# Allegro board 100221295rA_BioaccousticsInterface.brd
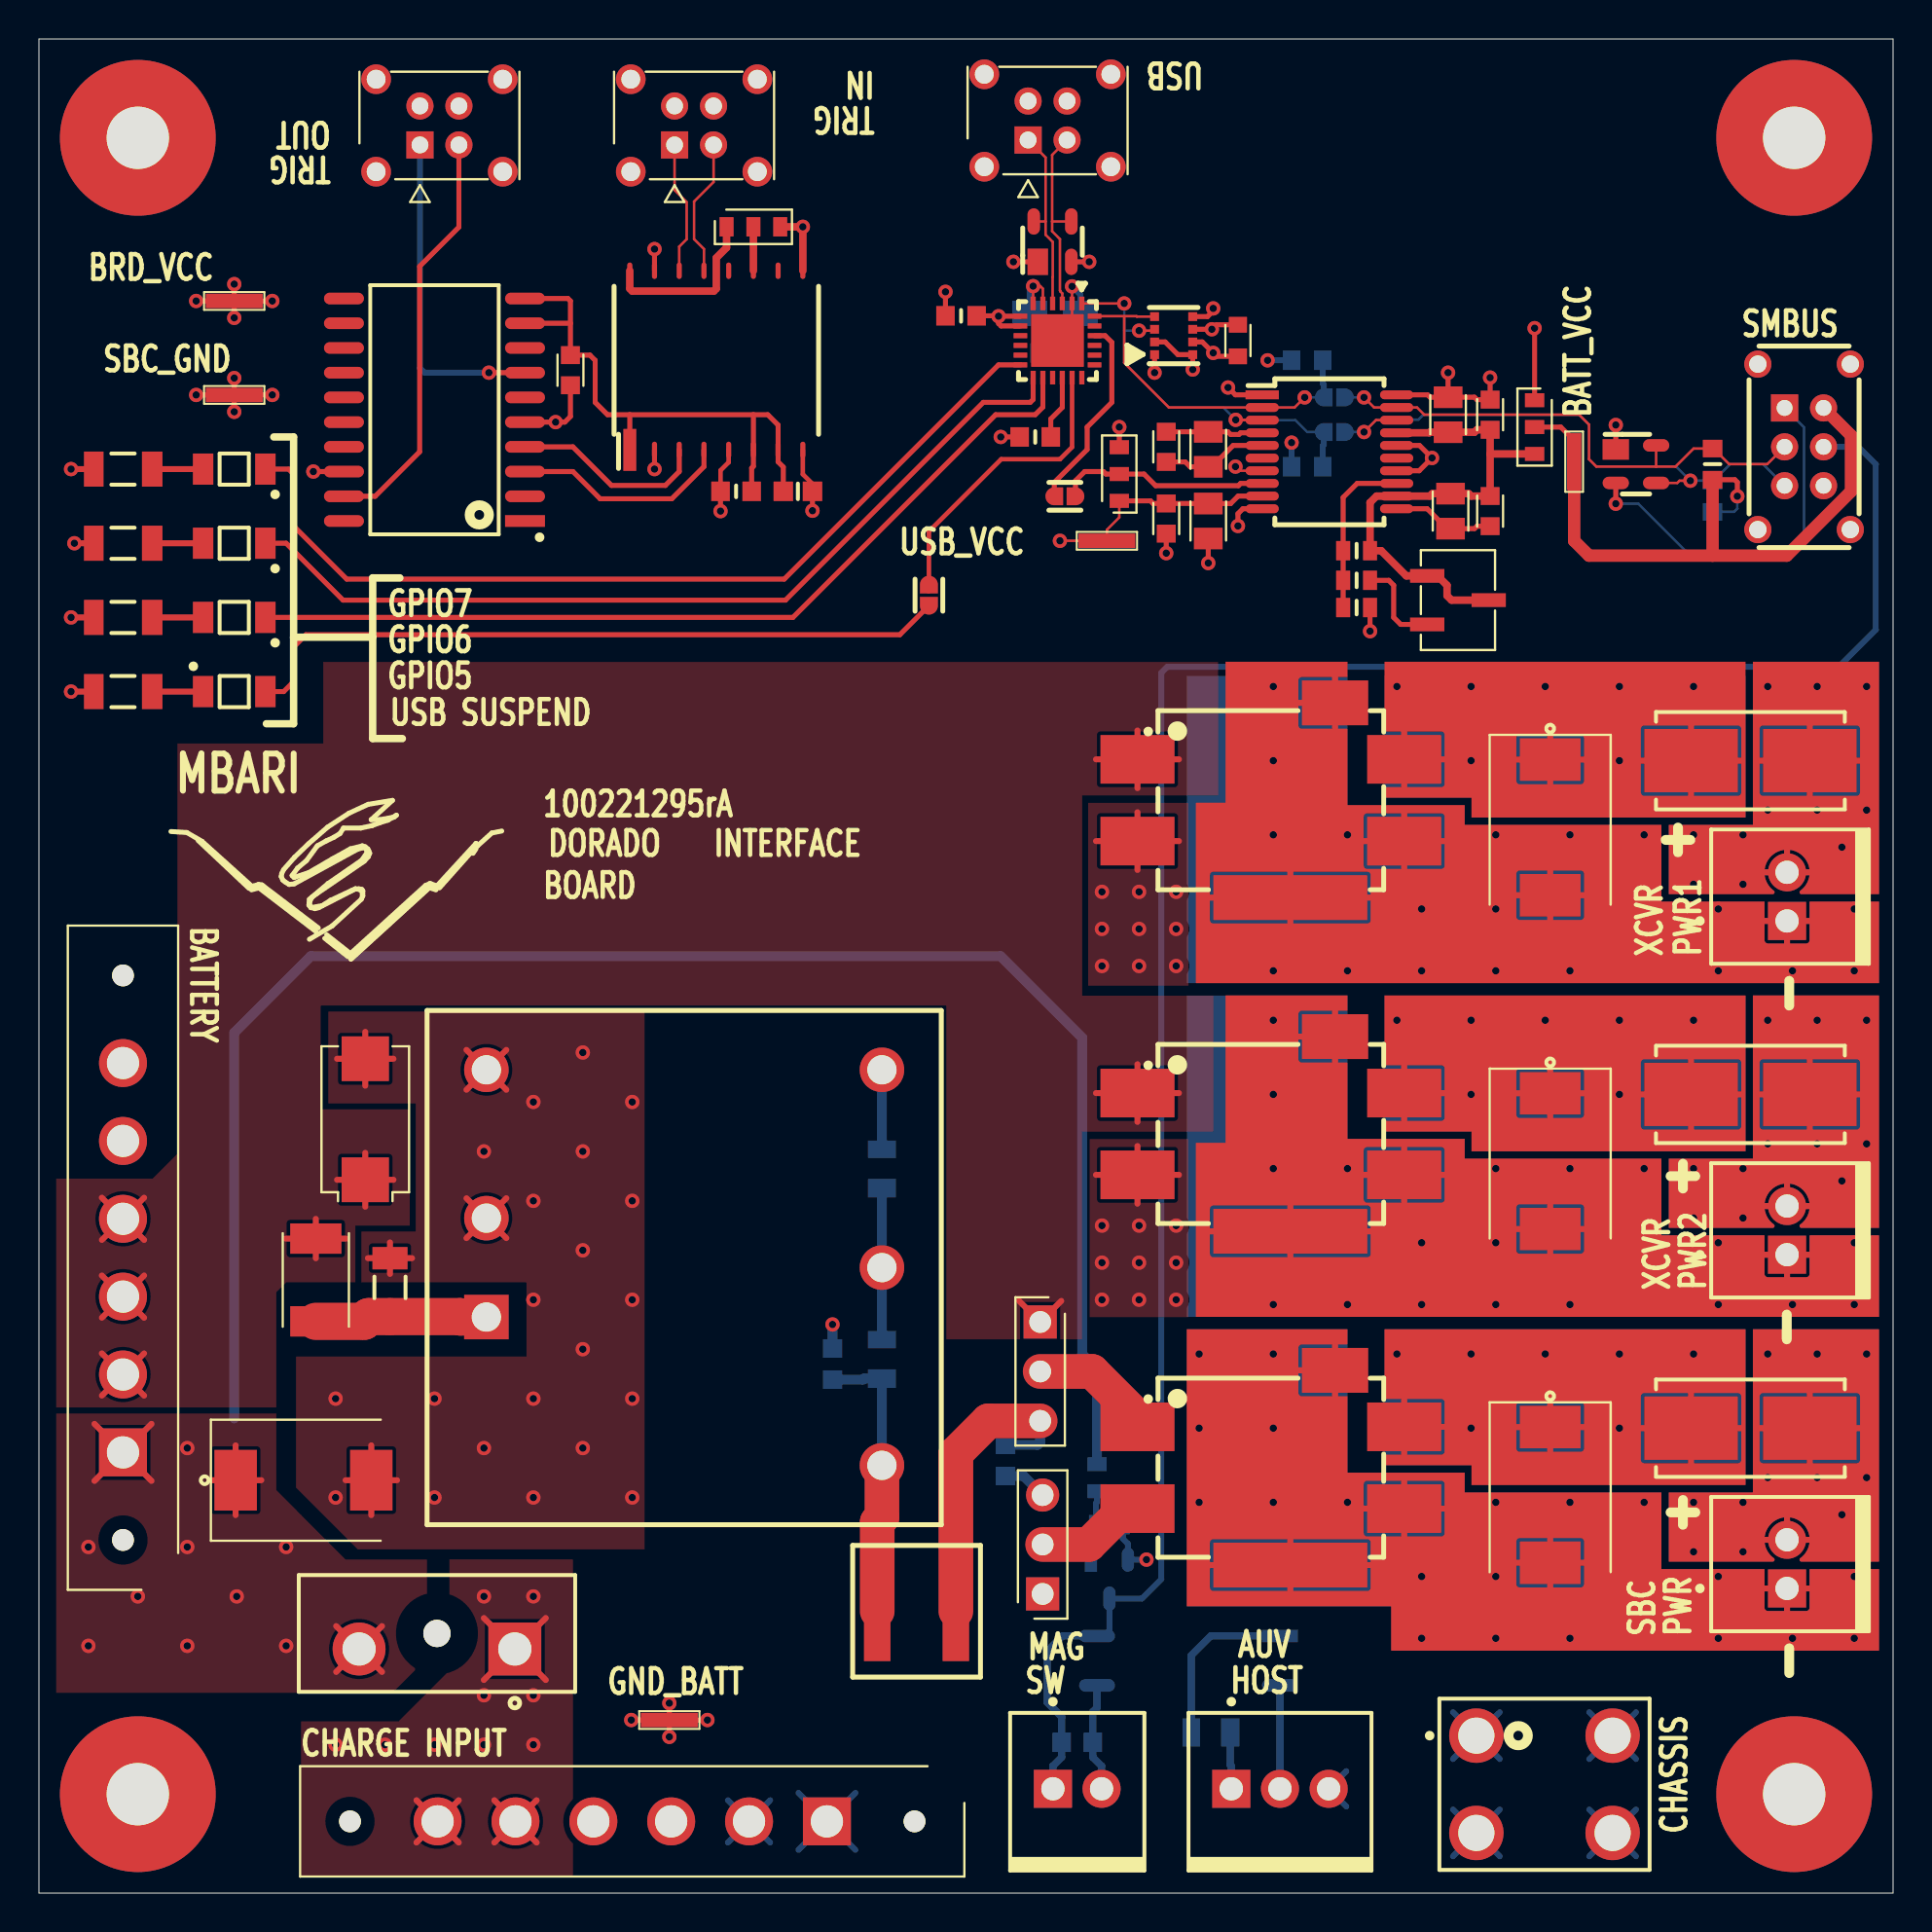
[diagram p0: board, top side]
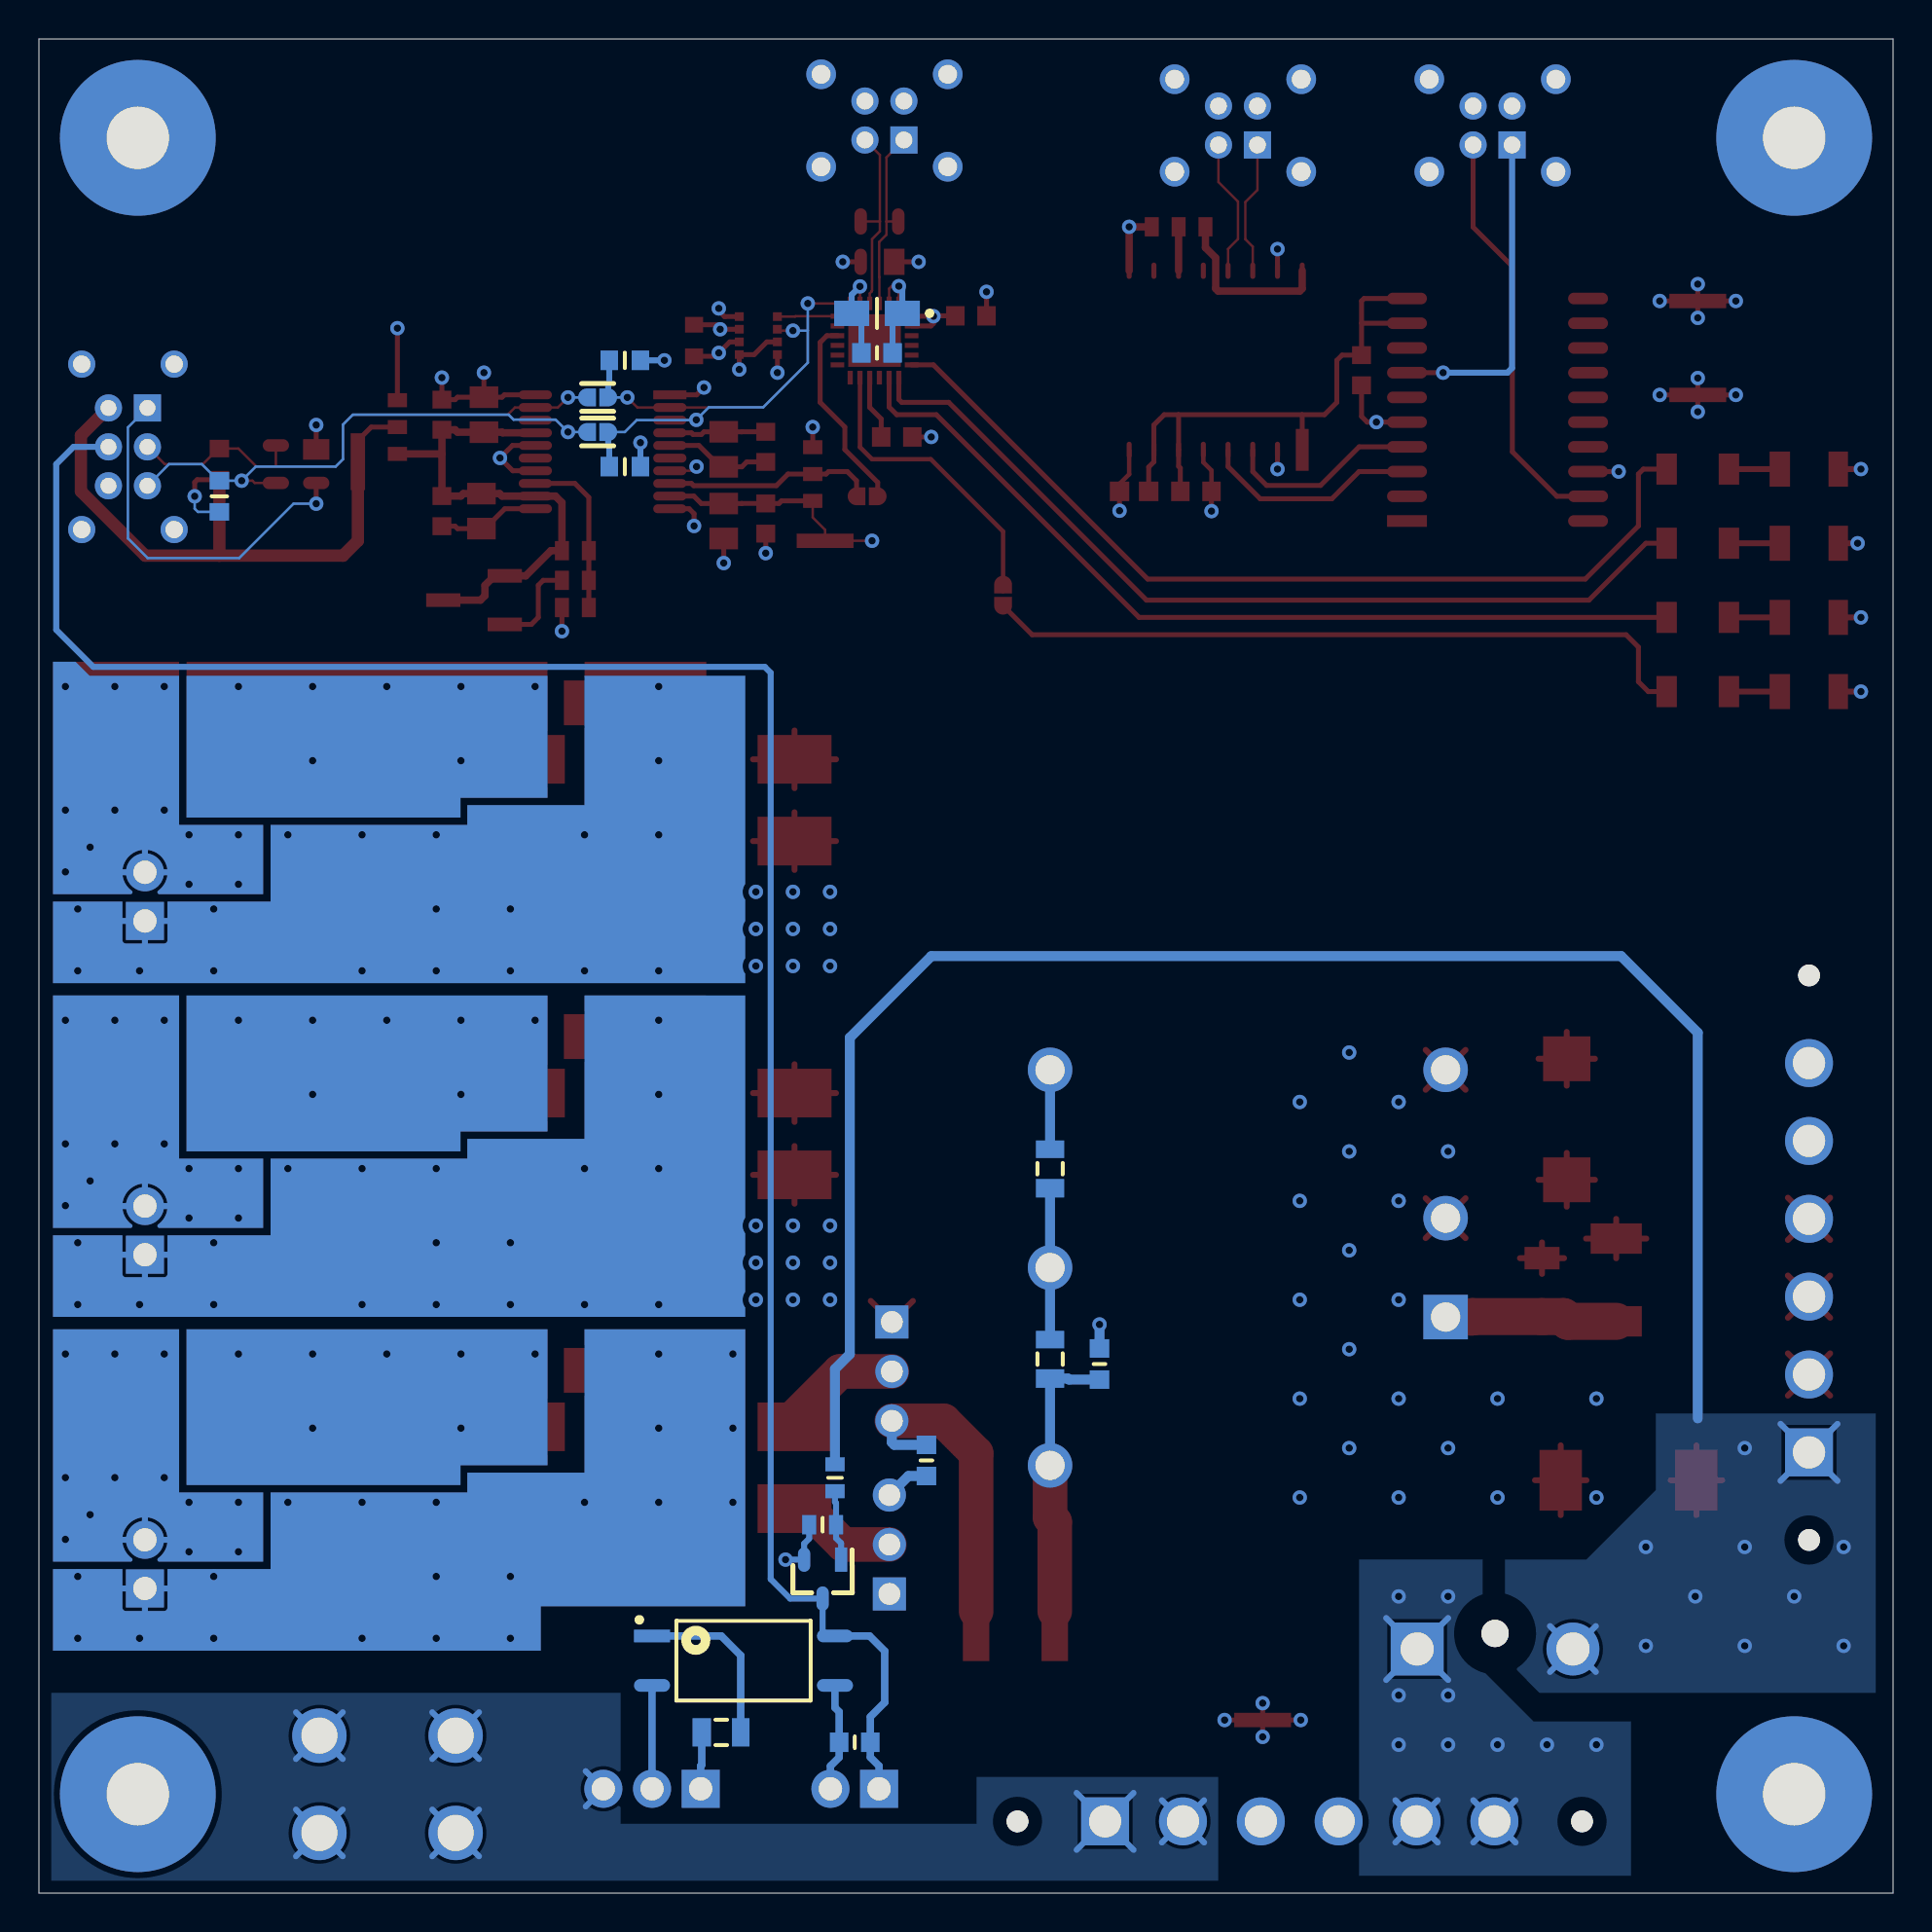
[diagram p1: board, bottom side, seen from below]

Outline 95.25 x 95.25 mm; copper layers: TOP, IN1, IN2, BOTTOM. Coordinates in mm from the lower left corner of the outline.
Outline path: 0,95.25 95.25,95.25 95.25,0 0,0 0,95.25

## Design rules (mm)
constraint set DEFAULT: min track width 0.127
net group AUV_BATT+: nets AUV_BATT+ N29578
net group BRD.SCL: nets BRD.SCL BRD.SDA
net group N26994: nets N26994 N26998
net group 3V3_ISO: nets 3V3_ISO N26987 N27684 N305001
net group BATT.SCL: nets BATT.SCL BATT.SDA BATT.VCC
net group BATT[0..4]: nets BATT.RESET
net group BATT_CHARGE: nets BATT_DISABLE N03532 N27268
net group BRD[0..4]: nets BRD.RESET
net group N02850: nets N02850 N03943 N21370
net group USB[0..3]: nets USB.D+ USB.D- USB.VCC

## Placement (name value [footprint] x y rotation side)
C1  1.0uF  [CAPC1608X90N]  53.34 7.75 0 bottom
C2  47uF  [CAPMP7343X430N]  16.76 39.75 90 top
C3  10uF  [CAPC3216X180N]  18.03 31.11 90 top
C4  1.0uF  [CAPC1608X90N]  40.77 27.18 90 bottom
C5  0.1uF  [CAPC1608X90N]  49.66 22.23 270 bottom
C6  4.7uF  [CAPMP3216X120N]  52.2 81.15 0 bottom
C7  0.1uF  [CAPC1608X90N]  52.2 79.12 0 bottom
C8  4.7uF  [CAPC1608X90N]  51.18 74.8 180 top
C9  0.1uF  [CAPC1608X90N]  47.37 81.03 180 top
C10  10uF  [CAPC2012X145L45N]  60.07 74.17 270 top
C11  0.10uF  [CAPC1608X87N]  57.91 74.3 270 top
C12  0.10uF  [CAPC1608X87N]  74.55 70.99 270 top
C13  10uF  [CAPC2012X145L45N]  72.52 70.99 270 top
C14  10uF  [CAPC2012X145L45N]  60.07 70.48 270 top
C15  0.10uF  [CAPC1608X87N]  57.91 70.61 270 top
C16  0.10uF  [CAPC1608X87N]  74.55 75.95 90 top
C17  10uF  [CAPC2012X145L45N]  72.39 75.95 90 top
C18  0.1uF  [CAPC1608X90N]  35.81 72.01 180 top
C19  10uF  [CAPC1608X100N]  38.99 72.01 0 top
C20  0.10uF  [CAPC1608X87N]  27.3 78.23 270 top
C21  0.1uF  [CAPC1608X80L30N]  61.59 79.76 270 top
D1  SMDJ22A  [DIOM7959X262N]  13.59 21.21 0 top
D2  SMDJ22A  [DIOM7959X262N]  77.64 54.74 270 top
D3  SMDJ22A  [DIOM7959X262N]  77.64 37.6 270 top
D4  SMDJ22A  [DIOM7959X262N]  77.64 20.45 270 top
D5  LTST-C150EKT  [LED_LTST-C150XXX]  10.03 65.53 180 top
D6  LTST-C150AKT  [LED_LTST-C150XXX]  10.03 69.34 180 top
D7  LTST-C150KSKT  [LED_LTST-C150XXX]  10.03 73.15 180 top
D8  LTST-C150KGKT  [LED_LTST-C150XXX]  10.03 61.72 0 top
F1  178.6764.0001  [LITTELFUSE_178-6764-0001]  24.45 12.54 180 top
F2  0154001.DRT  [FUSM9750X381N]  87.92 58.17 0 top
F3  0154001.DRT  [FUSM9750X381N]  87.92 41.03 0 top
F4  0154002.DRT  [FUSM9750X381N]  87.92 23.88 0 top
J1  M80-5000000M2-06-331-00-000  [HARWIN_M80-331-6PIN]  30.48 3.68 0 top
J2  1881558  [PHOENIX_1881558]  89.8 15.65 90 top
J3  1881558  [PHOENIX_1881558]  89.8 49.94 90 top
J4  1881561  [PHOENIX_1881561]  61.25 5.36 0 top
J5  1881558  [PHOENIX_1881558]  89.8 32.79 90 top
J6  M80-8530442  [HARWIN_M80-8530442]  33.66 90.81 180 top
J7  1881558  [PHOENIX_1881558]  52.09 5.36 0 top
J8  M80-8530442  [HARWIN_M80-8530442]  20.57 90.81 180 top
J9  M80-5000000M2-06-331-00-000  [HARWIN_M80-331-6PIN]  4.32 32.64 270 top
J10  M80-8530642  [HARWIN_M80-8530642]  90.68 74.3 90 top
J11  M80-8530442  [HARWIN_M80-8530442]  51.82 91.06 180 top
JP1  LS=0.100"  [HDRV3W64P254_3X1_762X254H1363B]  51.44 29.34 270 top
JP2  LS=0.100"  [HDRV3W64P254_3X1_762X254H1363B]  51.56 15.37 90 top
JR1  TBD  [MISC_0603-3P-JMPR]  76.83 75.31 270 top
JR2  TBD  [MISC_0603-3P-JMPR]  36.7 85.6 0 top
JR3  TBD  [MISC_0603-3P-JMPR]  55.5 72.9 90 top
L1  BNX024H01L  [MURATA_BNX02XH01_370]  63.28 56.14 0 top
L2  BNX024H01L  [MURATA_BNX02XH01_370]  63.28 39 0 top
L3  BNX024H01L  [MURATA_BNX02XH01_370]  63.28 21.85 0 top
L4  1uH  [INDM4532X340N]  14.22 31.5 270 top
L5  22uH  [COILCRAFT_XAL60XX-223]  45.09 14.48 0 top
NOREF  -  []  0 0 90 top
NOREF#2  -  []  0 0 0 top
NOREF#3  -  []  16 57.15 0 top
NOREF#4  -  []  -50.8 -76.2 0 top
NOREF#5  -  []  0 0 90 top
NOREF#6  -  [unnamed#2]  90.17 5.08 90 top
NOREF#7  -  []  0 0 0 top
NOREF#8  -  []  129.16 148.34 0 top
NOREF#9  -  []  0 0 90 top
NOREF#10  -  []  0 0 0 top
NOREF#11  -  [unnamed#2]  5.08 90.17 90 top
NOREF#12  -  [unnamed#2]  5.08 5.08 90 top
NOREF#13  -  [unnamed#2]  90.17 90.17 90 top
Q1  SI2308BDS-T1-E3  [VISHAY_SOT-23]  54.99 16.13 0 bottom
R1  1.00K  [RESC1608X50N]  54.36 21.34 270 bottom
R2  51.1K  [RESC1608X50N]  54.99 18.92 180 bottom
R3  TBD  [RESC2012X50N]  60.2 8.26 180 bottom
R4  TBD  [RESC2012X50N]  43.31 27.43 90 bottom
R5  TBD  [RESC2012X50N]  43.31 37.21 90 bottom
R6  4.7k  [RESC1609X55N]  65.15 73.28 180 bottom
R7  4.7k  [RESC1609X55N]  65.15 78.74 180 bottom
R8  4.7k  [RESC1609X55N]  85.98 71.75 270 bottom
R9  4.7k  [RESC1609X55N]  85.98 73.41 270 top
R10  511  [RESC3216X60N]  4.32 65.53 180 top
R11  511  [RESC3216X60N]  4.32 69.34 180 top
R12  TBD  [RESC1608X50N]  67.69 68.96 180 top
R13  10.0K  [RESC1608X50N]  67.69 67.44 180 top
R14  10.0K  [RESC1608X50N]  67.69 66.04 180 top
R15  10k  [BITE_44W]  72.9 66.42 270 top
R16  511  [RESC3216X60N]  4.32 73.15 180 top
R17  511  [RESC3216X60N]  4.32 61.72 180 top
SB1  0603  [MISC_JUMPER_SM0603]  52.7 71.75 0 top
SB2  0603  [MISC_JUMPER_SM0603]  66.55 75.06 0 bottom
SB3  0603  [MISC_JUMPER_SM0603]  66.55 76.83 0 bottom
SB4  0603  [MISC_JUMPER_SM0603]  45.72 66.67 270 top
ST1  8191  [SCREW-TERMINAL_8191]  77.34 5.59 0 top
U1  TCLT1006  [SOIC254P1015X230-4N]  59.05 11.94 180 bottom
U2  S24SE12002PDFA  [DELTA_S24SE]  33.15 32.13 0 top
U3  CP2112-F03-GMR  [SILAB_QFN24]  52.32 79.76 180 top
U4  SP0503BAHTG  [LITTELFUSE_SOT143]  52.07 84.84 0 top
U5  SP0503BAHTG  [LITTELFUSE_SOT143]  82.04 73.41 270 top
U6  ADM3260ARSZ  [ANALOG_RS-20]  66.29 74.04 270 top
U7  ADUM5202CRWZ  [ANALOG_RW-16]  34.8 78.74 0 top
U8  MAX3235ECWP+G36  [SOIC127P1032X265-20N]  20.32 76.2 180 top
U9  BME280  [BOSCH_BME280]  58.29 80.01 90 top
V1  SM_PAD  [MISC_SM-TP]  10.03 76.96 180 top
V2  SM_PAD  [MISC_SM-TP]  32.38 8.89 0 top
V3  SM_PAD  [MISC_SM-TP]  54.86 69.47 180 top
V4  SM_PAD  [MISC_SM-TP]  10.03 81.79 180 top
V5  SM_PAD  [MISC_SM-TP]  78.87 73.53 270 top

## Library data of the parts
C1 C3 C4 = CAP: signal model: DEFAULT_CAPACITOR_0.001pF_1_2
C2 = CAP_P: signal model: DEFAULT_CAPACITOR_4.7e+07pF_1_2
C5 C7 C9 C18 C20 C21 = CAP: signal model: DEFAULT_CAPACITOR_100000pF_1_2
C6 = CAP_P: signal model: DEFAULT_CAPACITOR_4.7e+06pF_1_2
C8 C10-C17 = CAP: signal model: DEFAULT_CAPACITOR_4.7e+06pF_1_2
C19 = CAP: signal model: DEFAULT_CAPACITOR_1e+07pF_1_2
D1-D4 = DIODE_TVS
D5-D8 = LED
F1-F4 = FUSEHOLDER_2T_2PIN
J1 J9 J10 = CON6
J2 J3 J5 J7 = CON2
J4 = CON3
J6 J8 J11 = CON4
JP1 JP2 = JUMPER_3PIN
JR1-JR3 = RES_3PIN-JMPR
L1-L3 = EMI_Block_Filter_BNXxxx
L4 L5 = IND
Q1 = MOSFET_I_EN_GSD
R1-R5 = RES: signal model: DEFAULT_RESISTOR_0.001OHM_1_2
R6-R9 R12-R14 = RES: signal model: DEFAULT_RESISTOR_4700OHM_1_2
R10 R11 R16 R17 = RES
R15 = POT_3PIN_2W
SB1-SB4 = SB_JUMPER
ST1 = SCREW-TERMINAL_8191SERIES
U1 = TCLT100x
U2 = DELTA_S24SE-SINGLE
U3 = CP2112
U4 U5 = LITTELFUSE_SP0503BAHT
U6 = ADM3260
U7 = ADUM5202
U8 = MAX3235E
U9 = BME280
V1-V5 = BLANK_PAD

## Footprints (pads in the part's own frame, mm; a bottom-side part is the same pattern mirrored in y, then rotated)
ANALOG_RS-20
  rect 0.457x1.707 smd: 1(-2.926,-3.454)
  oval 0.457x1.707 smd: 2(-2.276,-3.454) 3(-1.626,-3.454) 4(-0.975,-3.454) 5(-0.325,-3.454) 6(0.325,-3.454) 7(0.975,-3.454) 8(1.626,-3.454) 9(2.276,-3.454) 10(2.926,-3.454) 11(2.926,3.454) 12(2.276,3.454) 13(1.626,3.454) 14(0.975,3.454) 15(0.325,3.454) 16(-0.325,3.454) 17(-0.975,3.454) 18(-1.626,3.454) 19(-2.276,3.454) 20(-2.926,3.454)
ANALOG_RW-16
  rect 0.66x2.154 smd: 1(-4.445,-4.602)
  oval 0.259x0.841 smd: 2(-3.175,-4.602) 3(-1.905,-4.602) 4(-0.635,-4.602) 5(0.635,-4.602) 6(1.905,-4.602) 7(3.175,-4.602) 8(4.445,-4.602) 9(4.445,4.602) 10(3.175,4.602) 11(1.905,4.602) 12(0.635,4.602) 13(-0.635,4.602) 14(-1.905,4.602) 15(-3.175,4.602) 16(-4.445,4.602)
BITE_44W
  rect 0.701x1.76 smd: 1(-1.247,-1.58) 2(0,1.58) 3(1.247,-1.58)
BOSCH_BME280
  rect 0.447x0.457 smd: 1(-0.975,0.98) 2(-0.325,0.98) 3(0.325,0.98) 4(0.975,0.98) 5(0.975,-0.98) 6(0.325,-0.98) 7(-0.325,-0.98) 8(-0.975,-0.98)
CAPC1608X80L30N
  rect 0.81x0.93 smd: 1(-0.81,0) 2(0.81,0)
CAPC1608X87N
  rect 0.919x0.97 smd: 1(-0.775,0) 2(0.775,0)
CAPC1608X90N
  rect 0.95x1.001 smd: 1(-0.8,0) 2(0.8,0)
CAPC1608X100N
  rect 1.001x1.001 smd: 1(-0.749,0) 2(0.749,0)
CAPC2012X145L45N
  rect 1.11x1.471 smd: 1(-0.899,0) 2(0.899,0)
CAPC3216X180N
  rect 1.151x1.801 smd: 1(-1.501,0) 2(1.501,0)
CAPMP3216X120N
  rect 1.801x1.3 smd: 1(-1.3,0) 2(1.3,0)
CAPMP7343X430N
  rect 2.301x2.431 smd: 1(-3.109,0) 2(3.109,0)
COILCRAFT_XAL60XX-223
  rect 1.361x5.121 smd: 1(-2.019,0) 2(2.019,0)
DELTA_S24SE
  rect 2.286x2.286 hole 1.499: 1(-10.16,-2.54)
  round 2.286 hole 1.499: 2(-10.16,2.54) 3(-10.16,10.16) 4(10.16,10.16) 5(10.16,0) 6(10.16,-10.16)
DIOM7959X262N
  rect 2.179x3.119 smd: A(3.485,0) C(-3.485,0)
FUSM9750X381N
  rect 4.801x3.251 smd: 1(-3.051,0) 2(3.051,0)
HARWIN_M80-331-6PIN
  round 1.118 hole 2.261 unplated: (-14.501,0) (14.501,0)
  rect 2.464x2.464 hole 1.651: 1(10,0)
  round 2.464 hole 1.651: 2(5.999,0) 3(1.999,0) 4(-1.999,0) 5(-5.999,0) 6(-10,0)
HARWIN_M80-8530442
  round 1.524 hole 0.965: (-3.251,2.375) (-3.251,-2.375) (3.251,2.375) (3.251,-2.375)
  rect 1.397x1.397 hole 0.864: 1(1.001,1.001)
  round 1.397 hole 0.864: 2(-1.001,1.001) 3(1.001,-1.001) 4(-1.001,-1.001)
HARWIN_M80-8530642
  round 1.397 hole 0.889: (-4.249,2.375) (-4.249,-2.375) (4.249,2.375) (4.249,-2.375)
  rect 1.397x1.397 hole 0.813: 1(1.999,1.001)
  round 1.397 hole 0.813: 2(0,1.001) 3(-1.999,1.001) 4(1.999,-1.001) 5(0,-1.001) 6(-1.999,-1.001)
HDRV3W64P254_3X1_762X254H1363B
  rect 1.702x1.702 hole 1.118: 1(0,0)
  round 1.702 hole 1.118: 2(2.54,0) 3(5.08,0)
INDM4532X340N
  rect 1.56x2.629 smd: 1(-2.126,0) 2(2.126,0)
LED_LTST-C150XXX
  rect 1.049x1.6 smd: A(1.6,0) C(-1.6,0)
LITTELFUSE_178-6764-0001
  round 1.4 hole 2.799 unplated: (4,-0.8)
  rect 2.718x2.718 hole 1.702: 1(0,0)
  round 2.718 hole 1.702: 2(8.001,0)
LITTELFUSE_SOT143
  rect 1.057x1.351 smd: 1(-0.757,-1.036)
  oval 0.64x1.351 smd: 2(0.965,-1.036) 3(0.965,1.036) 4(-0.965,1.036)
MISC_0603-3P-JMPR
  rect 0.719x0.991 smd: 1(-1.379,0) 2(0,0) 3(1.379,0)
MISC_JUMPER_SM0603
  custom 0.227x0.227 smd: 1(-0.544,0) 2(0.544,0)
MISC_SM-TP
  rect 2.921x0.739 smd: 1(0,0)
MURATA_BNX02XH01_370
  rect 3.8x2.499 smd: 1(-6.85,2.101) 2(6.85,2.101) 3(-6.85,-2.101) 4(6.85,-2.101)
  rect 7.899x2.301 smd: 5(1.001,-5.001)
  rect 3.401x2.301 smd: 6(3.299,5.001)
PHOENIX_1881558
  rect 1.956x1.956 hole 1.194: 1(0,0)
  round 1.956 hole 1.194: 2(2.499,0)
PHOENIX_1881561
  rect 1.956x1.956 hole 1.194: 1(0,0)
  round 1.956 hole 1.194: 2(2.499,0) 3(5.001,0)
RESC1608X50N
  rect 0.719x0.991 smd: 1(-0.691,0) 2(0.691,0)
RESC1609X55N
  rect 0.899x1.001 smd: 1(-0.8,0) 2(0.8,0)
RESC2012X50N
  rect 0.95x1.45 smd: 1(-1.001,0)
  rect 0.899x1.45 smd: 2(1.001,0)
RESC3216X60N
  rect 1.049x1.801 smd: 1(-1.501,0)
  rect 1.001x1.801 smd: 2(1.501,0)
SCREW-TERMINAL_8191
  round 2.794 hole 1.854: 1(-3.5,2.499) 2(-3.5,-2.499) 3(3.5,-2.499) 4(3.5,2.499)
SILAB_QFN24
  rect 0.264x0.701 smd: 1(-1.25,-1.905) 2(-0.749,-1.905) 3(-0.249,-1.905) 4(0.249,-1.905) 5(0.749,-1.905) 6(1.25,-1.905) 13(1.25,1.905) 14(0.749,1.905) 15(0.249,1.905) 16(-0.249,1.905) 17(-0.749,1.905) 18(-1.25,1.905)
  rect 0.701x0.264 smd: 7(1.905,-1.25) 8(1.905,-0.749) 9(1.905,-0.249) 10(1.905,0.249) 11(1.905,0.749) 12(1.905,1.25) 19(-1.905,1.25) 20(-1.905,0.749) 21(-1.905,0.249) 22(-1.905,-0.249) 23(-1.905,-0.749) 24(-1.905,-1.25)
  rect 2.703x2.703 smd: 25(0,0)
SOIC127P1032X265-20N
  rect 2.05x0.599 smd: 1(-4.651,5.715)
  oval 2.05x0.599 smd: 2(-4.651,4.445) 3(-4.651,3.175) 4(-4.651,1.905) 5(-4.651,0.635) 6(-4.651,-0.635) 7(-4.651,-1.905) 8(-4.651,-3.175) 9(-4.651,-4.445) 10(-4.651,-5.715) 11(4.651,-5.715) 12(4.651,-4.445) 13(4.651,-3.175) 14(4.651,-1.905) 15(4.651,-0.635) 16(4.651,0.635) 17(4.651,1.905) 18(4.651,3.175) 19(4.651,4.445) 20(4.651,5.715)
SOIC254P1015X230-4N
  rect 1.849x0.65 smd: 1(-4.699,1.27)
  oval 1.849x0.65 smd: 2(-4.699,-1.27) 3(4.699,-1.27) 4(4.699,1.27)
unnamed#2
  round 8.001 hole 3.2: (0,0)
VISHAY_SOT-23
  rect 0.63x1.25 smd: 1(-0.95,-1.001)
  oval 0.63x1.25 smd: 2(0.95,-1.001) 3(0,1.001)

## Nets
3V3_ISO: C12.1 C13.1 C16.1 C17.1 JR1.3 R12.1 R15.1 R15.2(WIPER) U6.12 U6.17
5V_ISO: JR2.1 U7.16
GND_BATT: C1.2 C2.2 C3.2 C16.2 C17.2 D1.A J1.3 J1.4 J7.2 J9.5 J9.6 J10.6 JP2.1 L1.3(PSG) L2.3(PSG) Q1.2(S) R2.1 R14.1 U1.3 U2.2 U2.3 U5.1 U6.14 U6.16 U6.20 V2.1(CONN)
GND_EARTH: J1.1 J1.2 J4.3 ST1.1 ST1.2 ST1.3 ST1.4(IN_4)
GND_SBC: C6.2 C7.2 C8.2 C9.2 C14.2 C15.2 C18.2 C19.2 C20.2 C21.2 J8.3 J8.4 J11.3 JR3.3 R17.2 U3.2 U3.25 U4.1 U6.1 U6.7 U6.10 U7.2 U7.5 U7.8 U8.5 U8.18 U9.1 U9.5 U9.7 V1.1(CONN)
AUV_BATT+: J4.1 R3.1
AUV_BATT-: J4.2 U1.2(K)
BATT.RESET: J10.1 U5.2
BATT.SCL: J10.2 R9.1 SB3.2 U5.4(C3) U6.19
BATT.SDA: J10.3 R8.1 SB2.2 U5.3 U6.18
BATT.VCC: J10.4 JR1.2 R8.2 R9.2 V5.1(CONN)
BATT_CHARGE: D1.C F1.2 J9.1 R1.1
BATT_DISABLE: C1.1 J7.1 J10.5 Q1.3 U1.4
BATT_DISCHARGE: C2.1 J9.2 J9.3 J9.4 JP1.1 L1.1 L2.1 L4.1
BRD.RESET: U3.23
BRD.SCL: R7.1 SB3.1 U3.24 U6.2 U9.4
BRD.SDA: R6.1 SB2.1 U3.1 U6.3 U9.3
BRD.VCC: C6.1 C7.1 C21.1 JR1.1 R6.2 R7.2 R10.2 R11.2 R16.2 U3.5 U3.6 U9.2 U9.6(VDDIO) U9.8 V4.1(CONN)
CN_CPU_PWR: F4.2 J2.2
CN_CPU_RET: D4.A J2.1 L3.4 L3.5 L3.6
CN_TCVR1_PWR: F2.2 J3.2
CN_TCVR1_RET: D2.A J3.1 L1.4 L1.5 L1.6
CN_TCVR2_PWR: F3.2 J5.2
CN_TCVR2_RET: D3.A J5.1 L2.4 L2.5 L2.6
GPIO1: SB1.1 U3.22
GPIO2: U3.21
GPIO3: U3.20
GPIO4: U3.15
GPIO5: D5.C U3.14
GPIO6: D6.C U3.13
GPIO7: D7.C U3.12
NC_1: U6.15
PPS_ISO: U7.4 U8.3
TRIG_ISO: U7.3 U8.4
USB.D+: J11.2 U3.3 U4.3
USB.D-: J11.1 U3.4 U4.4(C3)
USB.VCC: C9.1 C14.1 C15.1 J11.4 JR3.1 U3.7 U3.8 U4.2 U6.9 V3.1(CONN)
USB.VCC_711: C18.1 C19.1 C20.1 U7.1 U7.6 U7.7 U8.9(VCC) U8.10
USB_SUSPEND: U3.11
USB_SUSPEND_N: SB4.1 U3.17
N02850: C4.1 L5.1 R4.1 U2.6
N03166: C4.2 C5.2 JP2.3 R5.2 U2.4
N03168: JP2.2 L3.3(PSG)
N03532: C3.1 L4.2 U2.1
N03830: J6.1 U7.14
N03943: R4.2 R5.1 U2.5(TRIM)
N04185: J8.2 U8.19
N04846: F1.1 J1.5 J1.6
N17598: J8.1 U8.7
N17685: J6.2 U7.13
N17697: J6.3 J6.4 JR2.3 U7.9 U7.15
N18654: D8.A SB4.2
N21370: C5.1 JP1.3 L5.2
N26987: C12.2 C13.2 U6.11
N26994: C10.1 C11.1 U6.4
N26998: C10.2 C11.2 U6.5
N27268: Q1.1 R1.2 R2.2
N27684: R12.2 R13.2 R14.2 U6.13(VSEL)
N29578: R3.2 U1.1
N30596: JR3.2 SB1.2 U6.8
N30925: JP1.2 L3.1
N31822: D2.C F2.1 L1.2
N33537: D3.C F3.1 L2.2
N33755: D4.C F4.1 L3.2
N0113014: C8.1 U3.16(VPP)
N169943: JR2.2 U7.11(VSEL)
N177140: D5.A R10.1
N177300: D6.A R11.1
N177460: D7.A R16.1
N182151: D8.C R17.1
N305001: R13.1 R15.3

Pads without a net: U3 9 10 18 19; U6 6; U7 10 12; U8 1 2 6 8 11 12 13 14 15 16 17 20

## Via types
v1: diameter 0.737, hole 0.381, TOP to BOTTOM, 234 vias

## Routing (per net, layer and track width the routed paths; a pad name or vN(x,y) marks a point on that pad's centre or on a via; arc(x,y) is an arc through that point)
3V3_ISO: length 26.9
  TOP w0.381: 74.55,73.93 C16.1 73.87,75.17 73.75,75.05 C17.1 71.46,75.05 71.43,75.02 U6.17 ; 74.55,73.93 JR1.3 ; 74.55,73.93 C12.1 73.57,71.77 73.45,71.89 C13.1 71.58,71.89 71.46,71.77 U6.12 68.72,71.77 68.38,71.43 R12.1 68.95,68.96 70.24,67.67 R15.1 71.85,67.67 72.34,67.18 72.34,66.65 72.57,66.42 R15.2
5V_ISO: length 8.9
  TOP w0.381: JR2.1 35.32,84.53 34.8,84 34.8,82.42 34.67,82.3 30.48,82.3 30.35,82.42 U7.16
GND_BATT: length 172.6
  TOP w0.254: C17.2 73.75,76.85 73.87,76.72 C16.2 v1(74.55,77.85) ; C17.2 71.46,76.85 71.34,76.97 U6.20 ; C17.2 v1(72.39,78.11) ; U6.14 70.91,73.07 v1(71.56,73.72) 70.92,74.37 U6.16 ; R14.1 v1(68.38,64.83) ; V2.1 v1(30.43,8.89) ; V2.1 v1(34.34,8.89) ; V2.1 v1(32.38,8.02) ; V2.1 v1(32.38,9.76) ; U5.1 v1(81.01,75.42)
  TOP w0.305: D1.A 17.07,23 ; D1.A 18.39,21.21 ; D1.A 17.07,19.42 ; D1.A 15.75,21.21 ; 56.43,52.56 L1.3 ; L1.3 58.56,54.04 ; L1.3 56.43,55.52 ; L1.3 54.3,54.04 ; L2.3 58.56,36.9 ; L2.3 56.43,35.42 ; L2.3 56.43,38.38 ; L2.3 54.3,36.9 ; 15.32,42.86 C2.2 ; C2.2 16.76,41.48 ; C2.2 16.76,44.24 ; C2.2 18.21,42.86 ; 21.96,43.31 U2.3 ; U2.3 24.01,41.27 ; U2.3 24.01,43.31 ; U2.3 21.96,41.27 ; 21.96,35.69 U2.2 ; U2.2 24.01,35.69 ; U2.2 24.01,33.65 ; U2.2 21.96,33.65 ; C3.2 18.03,33.42 ; C3.2 19.17,32.62 ; C3.2 16.9,32.62 ; C3.2 18.03,31.81
  IN1 w0.305: U2.2 24.01,33.65 ; U2.2 21.96,33.65 ; U2.2 24.01,35.69 ; U2.2 21.96,35.69 ; 90.97,73 J10.6 ; J10.6 92.39,73 ; J10.6 90.97,71.59 ; J10.6 92.39,71.59 ; J9.5 5.4,39.72 ; J9.5 3.23,39.72 ; J9.5 3.23,37.55 ; J9.5 5.4,37.55 ; 3.23,43.72 J9.6 ; J9.6 5.4,43.72 ; J9.6 3.23,41.55 ; J9.6 5.4,41.55 ; 31.39,2.6 J1.3 ; J1.3 33.56,2.6 ; J1.3 33.56,4.77 ; J1.3 31.39,4.77 ; 53.68,4.45 J7.2 ; J7.2 55.5,4.45 ; J7.2 53.68,6.26 ; J7.2 55.5,6.26 ; 50.48,16.45 JP2.1 ; JP2.1 52.64,16.45 ; JP2.1 52.64,14.28 ; JP2.1 50.48,14.28 ; 21.96,41.27 U2.3 ; U2.3 24.01,41.27 ; U2.3 21.96,43.31 ; U2.3 24.01,43.31 ; 27.4,2.6 J1.4 ; J1.4 29.57,2.6 ; J1.4 29.57,4.77 ; J1.4 27.4,4.77
  IN2 w0.305: J1.3 33.56,2.6 ; J1.3 31.39,4.77 ; J1.3 33.56,4.77 ; J1.3 31.39,2.6 ; J9.6 5.4,43.72 ; J9.6 5.4,41.55 ; J9.6 3.23,43.72 ; J9.6 3.23,41.55 ; 21.96,33.65 U2.2 ; U2.2 24.01,35.69 ; U2.2 24.01,33.65 ; U2.2 21.96,35.69 ; J9.5 5.4,39.72 ; J9.5 3.23,39.72 ; J9.5 5.4,37.55 ; J9.5 3.23,37.55 ; U2.3 24.01,43.31 ; U2.3 21.96,41.27 ; U2.3 21.96,43.31 ; U2.3 24.01,41.27 ; JP2.1 52.64,16.45 ; JP2.1 50.48,14.28 ; JP2.1 50.48,16.45 ; JP2.1 52.64,14.28 ; 53.68,4.45 J7.2 ; J7.2 55.5,4.45 ; J7.2 55.5,6.26 ; J7.2 53.68,6.26 ; J1.4 29.57,4.77 ; J1.4 27.4,4.77 ; J1.4 29.57,2.6 ; J1.4 27.4,2.6 ; 90.97,71.59 J10.6 ; J10.6 92.39,73 ; J10.6 92.39,71.59 ; J10.6 90.97,73
  BOTTOM w0.305: R2.1 55.68,18.21 55.94,17.95 Q1.2 v1(56.9,17.13)
  BOTTOM w0.381: U1.3 54.36,9.53 54.14,9.31 C1.2 54.14,6.97 54.59,6.53 J7.2
  vias: v1(15.24,25.4) v1(15.24,20.32) v1(20.32,25.4) v1(20.32,20.32) v1(22.86,38.1) v1(22.86,22.86) v1(25.4,40.64) v1(25.4,35.56) v1(25.4,30.48) v1(25.4,25.4) v1(25.4,20.32) v1(27.94,43.18) v1(27.94,38.1) v1(27.94,33.02) v1(27.94,27.94) v1(27.94,22.86) v1(30.48,40.64) v1(30.48,35.56) v1(30.48,30.48) v1(30.48,25.4) v1(30.48,20.32) v1(54.61,51.44) v1(54.61,49.53) v1(54.61,47.62) v1(54.61,34.29) v1(54.61,32.38) v1(54.61,30.48) v1(56.52,51.44) v1(56.52,49.53) v1(56.52,47.62) v1(56.52,34.29) v1(56.52,32.38) v1(56.52,30.48) v1(58.42,51.44) v1(58.42,49.53) v1(58.42,47.62) v1(58.42,34.29) v1(58.42,32.38) v1(58.42,30.48)
GND_EARTH: length 44.2
  BOTTOM w0.305: 67.16,4.45 J4.3 67.16,6.26 ; 72.64,4.29 ST1.2 ; ST1.2 75.04,4.29 ; ST1.2 75.04,1.89 ; ST1.2 72.64,1.89 ; 79.64,1.89 ST1.3 ; ST1.3 82.04,1.89 ; ST1.3 82.04,4.29 ; ST1.3 79.64,4.29 ; ST1.4 82.04,9.29 ; ST1.4 79.64,9.29 ; ST1.4 79.64,6.89 ; ST1.4 82.04,6.89 ; ST1.1 75.04,9.29 ; ST1.1 75.04,6.89 ; ST1.1 72.64,9.29 ; ST1.1 72.64,6.89 ; 35.39,4.77 J1.2 ; J1.2 37.56,4.77 ; J1.2 37.56,2.6 ; J1.2 35.39,2.6 ; J1.1 41.94,2.22 ; J1.1 39.02,5.15 ; J1.1 41.94,5.15 ; J1.1 39.02,2.22
GND_SBC: length 55.9
  TOP w0.127: v1(53.07,82.54) U3.2 53.07,80.51 U3.25 ; v1(61.47,73.28) 61.68,73.07 U6.7
  TOP w0.229: 39.74,72.39 39.24,72.89 U7.8 ; U7.5 35.43,73.5 35.01,73.08 35.01,72.39
  TOP w0.254: C14.2 v1(60.07,68.33) ; U7.2 v1(31.62,73.15) ; v1(61.09,77.34) 61.46,76.97 U6.1 ; U6.10 61.85,71.11 61.59,70.86 v1(61.59,70.23) ; U9.5 60.03,80.99 60.33,81.28 v1(60.33,81.41) ; C8.2 v1(49.41,74.8) ; U9.7 59.76,79.68 v1(60.33,79.12) 60.5,78.95 C21.2 ; V1.1 v1(10.03,77.83) ; V1.1 v1(8.08,76.96) ; V1.1 v1(10.03,76.1) ; V1.1 v1(11.99,76.96) ; U8.5 v1(26.54,75.56) 27.02,75.56 27.3,75.85 C20.2 ; C15.2 v1(57.91,68.83) ; U8.18 v1(14.1,73.03) ; U9.1 v1(57.31,78.11) ; JR3.3 v1(55.5,75.31) ; C9.2 v1(46.57,82.26) ; U4.1 v1(50.06,83.8) ; 35.01,72.39 C18.2 v1(35.01,70.99) ; v1(39.74,71.01) C19.2 39.74,72.39
  TOP w0.305: R17.2 v1(1.65,61.72)
  IN1 w0.305: J8.3 20.28,92.51 ; J8.3 18.86,91.1 ; J8.3 18.86,92.51 ; J8.3 20.28,91.1 ; 50.11,92.77 J11.3 ; J11.3 51.52,91.35 ; J11.3 50.11,91.35 ; J11.3 51.52,92.77 ; J8.4 22.28,91.1 ; J8.4 20.87,91.1 ; J8.4 20.87,92.51 ; J8.4 22.28,92.51
  BOTTOM w0.305: v1(53.07,82.54) 53.5,82.11 C6.2 53,80.65 C7.2
AUV_BATT+: length 2.9
  BOTTOM w0.381: J4.1 61.25,6.53 61.2,6.58 R3.1
AUV_BATT-: length 5.3
  BOTTOM w0.381: U1.2 J4.2
BATT.RESET: length 19.4
  TOP w0.254: U5.2 v1(81.01,71.37)
  BOTTOM w0.127: v1(81.01,71.37) 82.17,71.37 84.96,68.58 89.66,68.58 90.68,69.6 90.68,75.29 J10.1
BATT.SCL: length 27.3
  TOP w0.127: 83.08,73.28 80.01,73.28 79.63,73.66 79.63,75.44 79.12,75.95 71.17,75.95 70.79,76.32 U6.19 68.59,76.32 v1(68.07,76.83) ; 83.08,73.28 84.07,73.28 85,74.21 R9.1 86.03,74.21 86.83,73.41 88.79,73.41 J10.2 ; 83.08,73.28 U5.4
  BOTTOM w0.127: v1(68.07,76.83) SB3.2
BATT.SDA: length 29.9
  TOP w0.127: U6.18 68.68,75.67 v1(68.07,75.06) ; U5.3 84.16,72.44 84.28,72.56 v1(84.84,72.56)
  BOTTOM w0.127: J10.3 88.57,73.41 86.88,73.41 86.03,72.56 R8.1 v1(84.84,72.56) 84.11,73.28 80.01,73.28 79.63,73.66 79.63,75.44 79.12,75.95 71.12,75.95 70.87,75.69 68.71,75.69 v1(68.07,75.06) SB2.2
BATT.VCC: length 36.2
  TOP w0.254: JR1.2 78.18,75.31 78.87,74.62 V5.1 ; R9.2 87.12,72.61 87.25,72.48 v1(87.25,71.75)
  TOP w0.635: 85.98,68.71 79.63,68.71 78.87,69.47 V5.1 ; 85.98,68.71 89.79,68.71 93.09,72.01 93.09,74.88 J10.4 ; 85.98,68.71 R9.2
  BOTTOM w0.127: R8.2 87.08,70.95 87.25,71.12 v1(87.25,71.75)
BATT_CHARGE: length 125.2
  TOP w0.305: D1.C 11.42,21.21 ; D1.C 8.78,21.21 ; D1.C 10.1,23 ; D1.C 10.1,19.42 ; F1.2 17.62,11.36 ; F1.2 15.27,11.36 ; F1.2 15.27,13.71 ; F1.2 17.62,13.71 ; 2.85,24.1 J9.1 ; J9.1 5.78,21.18 ; J9.1 2.85,21.18 ; J9.1 5.78,24.1
  BOTTOM w0.127: 10.03,24.38 9.91,24.26
  BOTTOM w0.305: 2.85,24.1 J9.1 ; J9.1 2.85,21.18 ; J9.1 5.78,21.18 ; J9.1 5.78,24.1 ; 15.27,13.71 F1.2 ; F1.2 15.27,11.36 ; F1.2 17.62,13.71 ; F1.2 17.62,11.36
  BOTTOM w0.508: 10.03,24.38 10.03,44.2 13.97,48.13 49.4,48.13 53.59,43.94 53.59,27.69 54.36,26.92 R1.1
  vias: v1(2.54,17.78) v1(2.54,12.7) v1(5.08,15.24) v1(7.62,22.86) v1(7.62,17.78) v1(7.62,12.7) v1(10.16,15.24) v1(12.7,17.78) v1(12.7,12.7)
BATT_DISABLE: length 111.7
  BOTTOM w0.305: U1.4 54.74,13.21 54.99,13.46 Q1.3 56.66,15.13 57.66,16.13 57.66,62.69 57.96,62.99 92.46,62.99 94.36,64.9 94.36,73.41 93.47,74.3 J10.5
  BOTTOM w0.381: U1.4 52.58,13.21 51.8,12.43 51.8,9.79 52.54,9.06 C1.1 52.54,6.98 52.09,6.53 J7.1
BATT_DISCHARGE: length 46.7
  TOP w0.305: L1.1 56.43,59.72 ; L1.1 56.43,56.76 ; L1.1 54.3,58.24 ; L1.1 58.56,58.24 ; 3.23,25.55 J9.2 ; J9.2 5.4,27.72 ; J9.2 3.23,27.72 ; J9.2 5.4,25.55 ; 3.23,35.72 J9.4 ; J9.4 5.4,33.55 ; J9.4 5.4,35.72 ; J9.4 3.23,33.55 ; L4.1 15.77,33.62 ; L4.1 14.22,32.61 ; L4.1 14.22,34.63 ; L4.1 12.68,33.62 ; L2.1 56.43,42.58 ; L2.1 58.56,41.1 ; L2.1 54.3,41.1 ; L2.1 56.43,39.62 ; 52.52,30.42 JP1.1 50.35,30.42 ; C2.1 18.21,36.64 ; C2.1 16.76,38.02 ; C2.1 15.32,36.64 ; C2.1 16.76,35.26 ; 3.23,29.56 J9.3 ; J9.3 5.4,31.72 ; J9.3 5.4,29.56 ; J9.3 3.23,31.72
BRD.SCL: length 18.8
  TOP w0.127: 55.75,81.01 U3.24 ; 55.75,81.01 55.75,78.61 58.05,76.32 U6.2 64.51,76.32 v1(65.02,76.83) ; 55.75,81.01 56.39,81.01 56.41,80.99 U9.4
  BOTTOM w0.127: v1(65.02,76.83) SB3.1
  BOTTOM w0.305: R7.1 65.95,77.54 66,77.49 SB3.1
BRD.SDA: length 23.1
  TOP w0.127: v1(56.52,80.26) 57.24,80.26 U9.3 ; v1(55.75,81.66) U3.1 ; 61.49,75.67 U6.3 62.82,75.68 v1(61.48,75.68)
  BOTTOM w0.127: v1(55.75,81.66) 55.75,80.26 ; 55.75,80.26 v1(56.52,80.26) ; 55.75,80.26 55.75,78.62 58.04,76.33 60.84,76.33 v1(61.48,75.68) 61.5,75.67 64.54,75.67 65.15,75.06 SB2.1
  BOTTOM w0.305: SB2.1 66,74.4 65.95,74.35 R6.1
BRD.VCC: length 26.5
  TOP w0.127: U3.5 51.57,82.42 51.45,82.55 v1(51.07,82.55) U3.6
  TOP w0.254: V4.1 v1(11.99,81.79) ; V4.1 v1(8.08,81.79) ; V4.1 v1(10.03,80.92) ; V4.1 v1(10.03,82.65) ; C21.1 60.49,80.57 v1(60.25,80.34) U9.6 ; v1(59.27,78.27) U9.8 58.51,79.03 57.86,79.68 U9.2 ; JR1.1 v1(76.83,80.39)
  TOP w0.305: v1(1.65,65.53) R10.2 ; R11.2 v1(1.82,69.34) ; R16.2 v1(1.65,73.15)
  BOTTOM w0.305: v1(51.07,82.55) 50.9,82.37 C6.1 51.4,80.65 C7.1 ; R6.2 v1(64.35,74.51) ; R7.2 v1(63.12,78.74)
CN_CPU_PWR: length 16.2
  TOP w0.305: F4.2 90.97,25.74 ; F4.2 93.6,23.88 ; F4.2 88.34,23.88 ; F4.2 90.97,22.03 ; 88.6,18.15 J2.2 ; J2.2 91.01,18.15 ; J2.2 89.8,19.36
  BOTTOM w0.305: 88.6,18.15 J2.2 ; J2.2 91.01,18.15 ; J2.2 89.8,19.36
  vias: v1(85,20.07) v1(85,17.53) v1(87.54,20.07) v1(87.54,17.53) v1(88.81,27.69) v1(88.81,21.34) v1(91.35,27.69) v1(91.35,21.34) v1(92.62,19.44) v1(93.89,27.69) v1(93.89,21.34) v1(93.89,18.17)
CN_CPU_RET: length 36.5
  TOP w0.305: 75.84,16.97 D4.A ; D4.A 77.64,15.65 ; D4.A 79.43,16.97 ; D4.A 77.64,18.29 ; L3.5 64.28,18.23 ; L3.5 68.47,16.85 ; L3.5 64.28,15.47 ; L3.5 60.1,16.85 ; 89.8,14.44 J2.1 ; J2.1 88.6,15.65 ; J2.1 91.01,15.65 ; 70.13,18.27 L3.4 ; L3.4 68,19.75 ; L3.4 72.27,19.75 ; L3.4 70.13,21.23 ; 64.65,26.85 L3.6 ; L3.6 66.58,25.47 ; L3.6 66.58,28.23
  BOTTOM w0.305: 89.8,14.44 J2.1 ; J2.1 91.01,15.65 ; J2.1 88.6,15.65
  vias: v1(59.6,27.69) v1(59.6,23.88) v1(59.6,20.07) v1(63.41,27.69) v1(63.41,23.88) v1(63.41,20.07) v1(67.22,20.07) v1(71.03,16.26) v1(71.03,13.09) v1(74.84,20.07) v1(74.84,16.26) v1(74.84,13.09) v1(78.65,20.07) v1(78.65,13.09) v1(82.46,20.07) v1(86.27,16.26) v1(86.27,13.09) v1(90.08,13.09) v1(93.26,16.26) v1(93.26,13.09)
CN_TCVR1_PWR: length 16.2
  TOP w0.305: F2.2 93.6,58.17 ; F2.2 90.97,60.03 ; F2.2 90.97,56.32 ; F2.2 88.34,58.17 ; J3.2 89.8,53.65 ; J3.2 91.01,52.44 ; J3.2 88.6,52.44
  BOTTOM w0.305: J3.2 89.8,53.65 ; J3.2 91.01,52.44 ; J3.2 88.6,52.44
  vias: v1(85,54.36) v1(85,51.82) v1(87.54,54.36) v1(87.54,51.82) v1(88.81,61.98) v1(88.81,55.63) v1(91.35,61.98) v1(91.35,55.63) v1(92.62,53.73) v1(93.89,61.98) v1(93.89,55.63) v1(93.89,52.46)
CN_TCVR1_RET: length 36.5
  TOP w0.305: L1.5 68.47,51.14 ; L1.5 64.28,52.52 ; L1.5 64.28,49.76 ; L1.5 60.1,51.14 ; 68,54.04 L1.4 ; L1.4 70.13,55.52 ; L1.4 70.13,52.56 ; L1.4 72.27,54.04 ; D2.A 77.64,52.58 ; D2.A 75.84,51.26 ; D2.A 79.43,51.26 ; D2.A 77.64,49.94 ; 66.58,59.76 L1.6 ; L1.6 66.58,62.52 ; L1.6 64.65,61.14 ; J3.1 91.01,49.94 ; J3.1 89.8,48.73 ; J3.1 88.6,49.94
  BOTTOM w0.305: 88.6,49.94 J3.1 ; J3.1 89.8,48.73 ; J3.1 91.01,49.94
  vias: v1(63.41,61.98) v1(63.41,58.17) v1(63.41,54.36) v1(63.41,47.38) v1(67.22,54.36) v1(67.22,47.38) v1(71.03,50.55) v1(71.03,47.38) v1(74.84,54.36) v1(74.84,50.55) v1(74.84,47.38) v1(78.65,54.36) v1(78.65,47.38) v1(82.46,54.36) v1(86.27,50.55) v1(86.27,47.38) v1(90.08,47.38) v1(93.26,50.55) v1(93.26,47.38)
CN_TCVR2_PWR: length 16.2
  TOP w0.305: 88.6,35.29 J5.2 ; J5.2 89.8,36.5 ; J5.2 91.01,35.29 ; F3.2 93.6,41.03 ; F3.2 90.97,39.17 ; F3.2 90.97,42.89 ; F3.2 88.34,41.03
  BOTTOM w0.305: J5.2 89.8,36.5 ; J5.2 88.6,35.29 ; J5.2 91.01,35.29
  vias: v1(85,37.22) v1(85,34.68) v1(87.54,37.22) v1(87.54,34.68) v1(88.81,44.84) v1(88.81,38.49) v1(91.35,44.84) v1(91.35,38.49) v1(92.62,36.58) v1(93.89,44.84) v1(93.89,38.49) v1(93.89,35.31)
CN_TCVR2_RET: length 36.5
  TOP w0.305: 77.64,32.79 D3.A ; D3.A 75.84,34.11 ; D3.A 77.64,35.44 ; D3.A 79.43,34.11 ; 64.65,44 L2.6 ; L2.6 66.58,45.38 ; L2.6 66.58,42.62 ; 68,36.9 L2.4 ; L2.4 70.13,38.38 ; L2.4 70.13,35.42 ; L2.4 72.27,36.9 ; J5.1 91.01,32.79 ; J5.1 89.8,31.58 ; J5.1 88.6,32.79 ; 60.1,34 L2.5 ; L2.5 64.28,32.61 ; L2.5 64.28,35.38 ; L2.5 68.47,34
  BOTTOM w0.305: J5.1 91.01,32.79 ; J5.1 88.6,32.79 ; J5.1 89.8,31.58
  vias: v1(63.41,44.84) v1(63.41,41.03) v1(63.41,37.22) v1(63.41,30.23) v1(67.22,37.22) v1(67.22,30.23) v1(71.03,33.41) v1(71.03,30.23) v1(74.84,37.22) v1(74.84,33.41) v1(74.84,30.23) v1(78.65,37.22) v1(78.65,30.23) v1(82.46,37.22) v1(86.27,33.41) v1(86.27,30.23) v1(90.08,30.23) v1(93.26,33.41) v1(93.26,30.23)
GPIO1: length 10.2
  TOP w0.254: U3.22 54.77,80 55.12,79.66 55.12,76.58 53.85,75.31 53.85,74.16 52.16,72.47 SB1.1
GPIO5: length 45.9
  TOP w0.254: D5.C 38.73,65.53 49.15,75.95 51.18,75.95 51.57,76.34 U3.14
GPIO6: length 46
  TOP w0.254: U3.13 51.07,76.73 50.93,76.58 48.51,76.58 38.35,66.42 15.62,66.42 12.7,69.34 D6.C
GPIO7: length 47.2
  TOP w0.254: U3.12 49.3,78.51 38.29,67.5 15.81,67.5 13.08,70.23 13.08,72.9 12.83,73.15 D7.C
PPS_ISO: length 11.3
  TOP w0.254: U7.4 34.16,73.28 32.51,71.63 28.83,71.63 27.43,73.03 U8.3
TRIG_ISO: length 10.2
  TOP w0.254: U7.3 32.89,73.03 32.18,72.31 29.41,72.31 27.43,74.3 U8.4
USB.D+: length 9.9
  TOP w0.127: J11.2 52.05,89.29 52.05,85.87 ; 52.05,85.87 52.05,85.37 52.45,84.97 52.45,82.33 52.46,82.31 52.46,82.28 52.57,82.17 U3.3 ; 52.05,85.87 U4.3
USB.D-: length 9.5
  TOP w0.127: 51.71,85.87 51.71,89.16 J11.1 ; 51.71,85.87 U4.4 ; 51.71,85.87 51.71,85.19 52.08,84.82 52.08,83.02 52.08,83.01 U3.4
USB.VCC: length 56.7
  TOP w0.127: JR3.1 55.5,70.67 54.86,70.03 V3.1 v1(52.45,69.47)
  TOP w0.254: v1(49.3,81.01) 49.3,80.63 49.43,80.51 U3.8 ; v1(49.3,81.01) U3.7 ; v1(49.3,81.01) 49.28,81.03 C9.1 ; JR3.1 57.1,71.52 57.23,71.39 C15.1 59.14,71.39 59.14,71.38 C14.1 61.22,71.38 61.61,71.77 U6.9 ; U4.2 v1(53.95,83.8)
  IN2 w0.635: J11.4 56.02,92.06 57.28,90.81 57.28,87.88 55.63,86.23 53.95,86.23 ; 53.95,86.23 49.66,86.23 48.01,84.58 48.01,81.01 ; 53.95,86.23 v1(53.95,83.8) ; 48.01,81.01 48.01,73.1 51.64,69.47 v1(52.45,69.47) ; 48.01,81.01 v1(49.3,81.01)
USB.VCC_711: length 30.2
  TOP w0.254: 36.7,75.95 U7.6 36.7,73.29 36.61,73.21 C18.1 ; 36.7,75.95 37.44,75.95 37.97,75.42 U7.7 37.97,73.52 38.24,73.26 C19.1 ; 36.7,75.95 30.35,75.95 ; 30.35,75.95 U7.1 ; 30.35,75.95 29.21,75.95 28.57,76.58 28.57,78.74 28.31,79.01 C20.1 27.3,80.64 ; 27.3,80.64 27.3,81.79 27.18,81.92 U8.10 ; 27.3,80.64 24.97,80.64
USB_SUSPEND_N: length 15.8
  TOP w0.229: 45.72,66.88 SB4.1 45.72,69.95 49.43,73.66 52.45,73.66 53.07,74.28 U3.17
N02850: length 14.6
  TOP w1.778: L5.1 43.07,19.06 43.31,19.3 U2.6
  BOTTOM w0.508: U2.6 R4.1 42.39,26.43 42.33,26.38 C4.1
N03166: length 28.4
  IN1 w0.305: JP2.3 52.38,19.63 ; JP2.3 50.75,21.26 ; JP2.3 52.38,21.26 ; JP2.3 50.75,19.63 ; U2.4 44.33,43.31 ; U2.4 42.28,43.31 ; U2.4 44.33,41.27 ; U2.4 42.28,41.27
  IN2 w0.305: JP2.3 52.38,19.63 ; JP2.3 52.38,21.26 ; JP2.3 50.75,19.63 ; JP2.3 50.75,21.26 ; 42.28,43.31 U2.4 ; U2.4 44.33,43.31 ; U2.4 42.28,41.27 ; U2.4 44.33,41.27
  BOTTOM w0.508: JP2.3 50.58,21.42 C5.2 ; C4.2 v1(40.77,29.21) ; R5.2 U2.4
N03168: length 5.6
  TOP w1.778: JP2.2 53.94,17.91 55.78,19.75 L3.3
N03532: length 8.9
  TOP w1.905: U2.1 21.65,29.59 21.63,29.61 C3.1 16.94,29.61 16.7,29.37 L4.2
N03830: length 6.9
  TOP w0.127: U7.14 32.89,84.58 33.27,84.96 33.27,86.87 32.65,87.49 J6.1
N03943: length 7.8
  BOTTOM w0.508: R4.2 U2.5 R5.1
N04185: length 21.4
  TOP w0.254: U8.19 17.27,71.75 19.56,74.04 19.56,83.57 21.57,85.58 J8.2
N04846: length 42.5
  TOP w0.305: 23.4,2.6 J1.5 ; J1.5 25.57,4.77 ; J1.5 25.57,2.6 ; J1.5 23.4,4.77 ; 19.4,4.77 J1.6 ; J1.6 21.56,4.77 ; J1.6 19.4,2.6 ; J1.6 21.56,2.6 ; F1.1 26.04,10.95 ; F1.1 26.04,14.13 ; F1.1 22.86,14.13 ; F1.1 22.86,10.95
  BOTTOM w0.305: 22.86,14.13 F1.1 ; F1.1 26.04,10.95 ; F1.1 26.04,14.13 ; F1.1 22.86,10.95 ; J1.6 21.56,2.6 ; J1.6 19.4,4.77 ; J1.6 21.56,4.77 ; J1.6 19.4,2.6 ; 23.4,4.77 J1.5 ; J1.5 25.57,4.77 ; J1.5 25.57,2.6 ; J1.5 23.4,2.6
  vias: v1(15.24,7.62) v1(17.78,7.62) v1(20.32,7.62) v1(22.86,15.24) v1(22.86,10.16) v1(22.86,7.62) v1(25.4,15.24) v1(25.4,10.16) v1(25.4,7.62)
N17598: length 17
  TOP w0.254: U8.7 v1(23.11,78.11)
  BOTTOM w0.305: J8.1 19.57,78.34 19.81,78.11 v1(23.11,78.11)
N17685: length 7.1
  TOP w0.127: U7.13 34.16,84.46 33.66,84.97 33.66,86.9 34.66,87.9 J6.2
N17697: length 20.6
  TOP w0.254: U7.15 v1(31.62,84.45)
  TOP w0.381: JR2.3 v1(39.24,85.6) U7.9
  IN1 w0.305: 33.95,92.51 J6.4 ; J6.4 33.95,91.1 ; J6.4 35.36,92.51 ; J6.4 35.36,91.1 ; J6.3 33.36,91.1 ; J6.3 31.95,91.1 ; J6.3 31.95,92.51 ; J6.3 33.36,92.51
  IN2 w0.305: J6.4 35.36,91.1 ; J6.4 35.36,92.51 ; J6.4 33.95,91.1 ; J6.4 33.95,92.51 ; 31.95,92.51 J6.3 ; J6.3 33.36,92.51 ; J6.3 33.36,91.1 ; J6.3 31.95,91.1
N18654: length 37
  TOP w0.254: D8.A 12.57,61.72 13.08,62.23 13.08,64.01 13.72,64.64 44.23,64.64 45.71,66.13 SB4.2
N21370: length 16.1
  TOP w1.778: L5.2 47.1,22.59 48.77,24.26 JP1.3
  BOTTOM w0.508: C5.1 51.31,23.03 51.44,23.15 JP1.3
N26987: length 5.3
  TOP w0.254: U6.11 71.32,71.11 72.34,70.09 C13.2 73.75,70.09 73.87,70.22 C12.2
N26994: length 5
  TOP w0.254: C11.1 59.14,75.07 59.14,75.07 C10.1 61.08,75.07 61.22,74.93 61.65,74.93 61.73,75.02 U6.4
N26998: length 5.5
  TOP w0.254: C11.2 58.89,73.52 59.14,73.27 C10.2 60.25,73.27 61.35,74.37 U6.5
N27268: length 3.6
  BOTTOM w0.305: R1.2 54.36,20.09 54.3,20.04 R2.2 54.3,18.23 54.04,17.98 Q1.1
N27684: length 8.7
  TOP w0.254: R14.2 R13.2 R12.2 67,71.7 67.72,72.42 U6.13
N29578: length 8.9
  BOTTOM w0.381: U1.1 60.2,13.21 59.2,12.21 R3.2
N30596: length 10.9
  TOP w0.254: U6.8 61.73,72.42 61.62,72.3 57.37,72.3 56.77,72.9 JR3.2 54.81,72.9 54.68,73.03 53.72,73.03 53.25,72.55 SB1.2
N30925: length 6.5
  TOP w1.778: JP1.2 54.1,26.8 56.43,24.47 L3.1
N31822: length 20.3
  TOP w0.305: D2.C 77.64,59.55 ; D2.C 75.84,58.23 ; D2.C 77.64,56.91 ; D2.C 79.43,58.23 ; 70.13,56.76 L1.2 ; L1.2 72.27,58.24 ; L1.2 70.13,59.72 ; F2.1 87.5,58.17 ; F2.1 82.24,58.17 ; F2.1 84.87,60.03 ; F2.1 84.87,56.32
  vias: v1(69.76,61.98) v1(73.57,61.98) v1(73.57,58.17) v1(77.38,61.98) v1(81.19,61.98) v1(81.19,58.17) v1(85,61.98)
N33537: length 20.3
  TOP w0.305: F3.1 84.87,42.89 ; F3.1 87.5,41.03 ; F3.1 82.24,41.03 ; F3.1 84.87,39.17 ; D3.C 77.64,42.41 ; D3.C 75.84,41.08 ; D3.C 79.43,41.08 ; D3.C 77.64,39.76 ; 70.13,39.62 L2.2 ; L2.2 70.13,42.58 ; L2.2 72.27,41.1
  vias: v1(69.76,44.84) v1(73.57,44.84) v1(73.57,41.03) v1(77.38,44.84) v1(81.19,44.84) v1(81.19,41.03) v1(85,44.84)
N33755: length 20.3
  TOP w0.305: L3.2 70.13,25.43 ; L3.2 70.13,22.47 ; L3.2 72.27,23.95 ; F4.1 84.87,25.74 ; F4.1 84.87,22.03 ; F4.1 87.5,23.88 ; F4.1 82.24,23.88 ; D4.C 77.64,25.26 ; D4.C 77.64,22.62 ; D4.C 79.43,23.94 ; D4.C 75.84,23.94
  vias: v1(69.76,27.69) v1(73.57,27.69) v1(73.57,23.88) v1(77.38,27.69) v1(81.19,27.69) v1(81.19,23.88) v1(85,27.69)
N0113014: length 3.3
  TOP w0.254: U3.16 52.57,76.32 51.98,75.73 C8.1
N169943: length 2.3
  TOP w0.381: JR2.2 U7.11
N177140: length 2.6
  TOP w0.305: D5.A R10.1
N177300: length 2.6
  TOP w0.305: D6.A R11.1
N177460: length 2.6
  TOP w0.305: D7.A R16.1
N182151: length 2.6
  TOP w0.305: D8.C R17.1
N305001: length 4.8
  TOP w0.254: R15.3 69.95,65.17 69.6,65.53 69.6,67.18 69.34,67.44 R13.1

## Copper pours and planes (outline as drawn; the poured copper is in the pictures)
GND_BATT on TOP: 14.86,45.34 31.11,45.34 31.11,17.65 16.38,17.65 13.21,20.83 13.21,27.56 25.05,27.56 25.05,31.37 16.51,31.37 16.51,34.04 19.3,34.04 19.3,40.51 14.86,40.51
GND_BATT on TOP: 53.98,38.73 53.98,29.59 59.05,29.59 59.05,38.73
GND_BATT on TOP: 53.85,56.01 53.85,46.61 59.05,46.61 59.05,56.01
GND_BATT on IN1, IN2: 69.34,14.61 57.91,14.61 57.91,0.64 0.64,0.64 0.64,59.05 14.61,59.05 14.61,63.25 67.06,63.25 67.06,78.87 94.61,78.87 94.61,12.19 69.34,12.19 ; 1 cut-out
GND_EARTH on BOTTOM: 94.61,0.64 94.61,10.29 65.37,10.29 65.37,3.56 47.08,3.56 47.08,5.97 34.67,5.97 34.67,0.64
GND_SBC on IN1: 0.64,94.61 0.64,59.56 14.1,59.56 14.1,64.01 66.42,64.01 66.42,79.63 94.61,79.63 94.61,94.61 41.15,94.61 41.15,80.01 27.94,80.01 27.94,94.61
(no net) on TOP: 60.96,63.25 60.96,56.01 59.44,56.01 59.44,46.74 94.53,46.74 94.53,50.93 83.35,50.93 83.35,54.87 73.24,54.87 73.24,55.89 67.22,55.89 67.22,63.25
(no net) on TOP: 60.96,38.54 59.44,38.54 59.44,29.6 94.53,29.6 94.53,33.79 83.35,33.79 83.35,37.73 73.24,37.73 73.24,38.74 67.22,38.74 67.22,46.11 60.96,46.11
(no net) on TOP, BOTTOM: 69.13,63.25 69.13,56.27 73.59,56.27 73.59,55.25 87.67,55.25 87.67,63.25
(no net) on TOP, BOTTOM: 69.13,46.11 69.13,39.12 73.59,39.12 73.59,38.11 87.67,38.11 87.67,46.11
(no net) on TOP, BOTTOM: 83.73,20.58 83.73,17.03 94.53,17.03 94.53,28.96 88.05,28.96 88.05,20.58
(no net) on TOP, BOTTOM: 58.97,28.96 58.97,14.73 69.47,14.73 69.47,12.45 94.53,12.45 94.53,16.64 83.35,16.64 83.35,20.58 73.24,20.58 73.24,21.6 67.22,21.6 67.22,28.96
(no net) on TOP, BOTTOM: 83.73,54.87 83.73,51.32 94.53,51.32 94.53,63.25 88.05,63.25 88.05,54.87
(no net) on TOP, BOTTOM: 69.13,28.96 69.13,21.98 73.59,21.98 73.59,20.96 87.67,20.96 87.67,28.96
(no net) on TOP, BOTTOM: 83.73,37.73 83.73,34.17 94.53,34.17 94.53,46.11 88.05,46.11 88.05,37.73
(no net) on BOTTOM: 58.97,63.25 58.97,46.74 94.53,46.74 94.53,50.93 83.35,50.93 83.35,54.87 73.24,54.87 73.24,55.89 67.22,55.89 67.22,63.25
(no net) on BOTTOM: 58.97,46.11 58.97,29.6 94.53,29.6 94.53,33.79 83.35,33.79 83.35,37.73 73.24,37.73 73.24,38.74 67.22,38.74 67.22,46.11
BATT_CHARGE on TOP, BOTTOM: 0.89,24.64 0.89,10.29 18.16,10.29 19.94,12.06 19.94,17.13 15.76,17.13 12.19,20.7 12.19,24.64
BATT_DISCHARGE on TOP: 14.61,63.25 60.58,63.25 60.58,56.39 53.59,56.39 53.59,46.1 60.33,46.1 60.33,39.12 53.58,39.12 53.58,28.45 46.61,28.45 46.61,45.59 14.48,45.59 14.48,40.26 19.05,40.26 19.05,34.29 16.26,34.29 16.26,31.37 12.7,31.37 12.19,30.86 12.19,24.89 0.89,24.89 0.89,36.7 5.84,36.7 7.11,37.97 7.11,59.05 14.61,59.05
BRD.VCC on IN2: 0.64,59.56 0.64,94.61 27.94,94.61 27.94,80.01 41.15,80.01 41.15,94.61 94.61,94.61 94.61,79.63 66.42,79.63 66.42,64.01 14.1,64.01 14.1,59.56 ; 2 cut-outs
CN_CPU_PWR on TOP (solid shape): outline of 121 points within 83.73,17.03 94.53,28.96
CN_CPU_PWR on BOTTOM (solid shape): 94.53,17.03 90.55,17.03 90.45,17.1 90.49,17.21 90.84,17.62 90.97,18.15 89.8,19.31 88.64,18.15 88.77,17.62 89.12,17.21 89.16,17.1 89.06,17.03 83.73,17.03 83.73,20.58 88.05,20.58 88.05,28.96 94.53,28.96
CN_CPU_RET on TOP (solid shape): outline of 168 points within 58.97,12.45 94.53,28.96
CN_CPU_RET on BOTTOM (solid shape): 67.22,21.6 73.24,21.6 73.24,20.58 83.35,20.58 83.35,16.64 88.65,16.64 88.65,14.67 88.7,14.54 88.83,14.49 90.78,14.49 90.91,14.54 90.96,14.67 90.96,16.64 94.53,16.64 94.53,12.45 69.47,12.45 69.47,14.73 58.97,14.73 58.97,28.96 67.22,28.96
CN_TCVR1_PWR on TOP (solid shape): outline of 121 points within 83.73,51.32 94.53,63.25
CN_TCVR1_PWR on BOTTOM (solid shape): 94.53,51.32 90.55,51.32 90.45,51.39 90.49,51.5 90.84,51.91 90.97,52.44 89.8,53.6 88.64,52.44 88.77,51.91 89.12,51.5 89.16,51.39 89.06,51.32 83.73,51.32 83.73,54.87 88.05,54.87 88.05,62.53 92.65,62.53 93.37,63.25 94.53,63.25
CN_TCVR1_RET on TOP (solid shape): outline of 168 points within 59.44,46.74 94.53,63.25
CN_TCVR1_RET on BOTTOM (solid shape): 67.22,55.89 73.24,55.89 73.24,54.87 83.35,54.87 83.35,50.93 88.65,50.93 88.65,48.96 88.7,48.83 88.83,48.78 90.78,48.78 90.91,48.83 90.96,48.96 90.96,50.93 94.53,50.93 94.53,46.74 58.97,46.74 58.97,47.22 59.1,47.62 58.97,48.03 58.97,49.13 59.1,49.53 58.97,49.93 58.97,51.03 59.1,51.44 58.97,51.84 58.97,62.53 67.22,62.53
CN_TCVR2_PWR on TOP (solid shape): outline of 121 points within 83.73,34.17 94.53,46.11
CN_TCVR2_PWR on BOTTOM (solid shape): 94.53,34.17 90.55,34.17 90.45,34.24 90.49,34.35 90.84,34.77 90.97,35.29 89.8,36.45 88.64,35.29 88.77,34.77 89.12,34.35 89.16,34.24 89.06,34.17 83.73,34.17 83.73,37.73 88.05,37.73 88.05,46.11 94.53,46.11
CN_TCVR2_RET on TOP (solid shape): outline of 168 points within 59.44,29.6 94.53,46.11
CN_TCVR2_RET on BOTTOM (solid shape): 67.22,38.74 73.24,38.74 73.24,37.73 83.35,37.73 83.35,33.79 88.65,33.79 88.65,31.82 88.7,31.69 88.83,31.64 90.78,31.64 90.91,31.69 90.96,31.82 90.96,33.79 94.53,33.79 94.53,29.6 58.97,29.6 58.97,30.08 59.1,30.48 58.97,30.88 58.97,31.98 59.1,32.38 58.97,32.79 58.97,33.89 59.1,34.29 58.97,34.69 58.97,46.11 67.22,46.11
N03166 on IN1, IN2: 36.83,45.21 36.83,0.64 48.52,0.64 48.52,18.92 53.59,18.92 53.59,25.53 46.23,25.53 46.23,45.21
N04846 on TOP, BOTTOM: 13.46,8.82 13.46,0.89 27.43,0.89 27.43,17.14 21.08,17.14 21.08,11.43 18.47,8.82
N17697 on IN1, IN2: 29.34,94.61 29.34,81.79 40.01,81.79 40.01,94.61
N31822 on TOP (solid shape): outline of 103 points within 69.13,55.25 87.67,63.25
N31822 on BOTTOM (solid shape): 87.67,55.25 73.59,55.25 73.59,56.27 69.13,56.27 69.13,62.53 87.67,62.53
N33537 on TOP (solid shape): outline of 103 points within 69.13,38.11 87.67,46.11
N33537 on BOTTOM (solid shape): 87.67,38.11 73.59,38.11 73.59,39.12 69.13,39.12 69.13,46.11 87.67,46.11
N33755 on TOP (solid shape): outline of 103 points within 69.13,20.96 87.67,28.96
N33755 on BOTTOM (solid shape): 87.67,20.96 73.59,20.96 73.59,21.98 69.13,21.98 69.13,28.96 87.67,28.96

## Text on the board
User.Comments: CR_CH1_2 | CR_CH1_1
Ref Des/Silkscreen Top: BRD_VCC | SBC_GND | CHARGE INPUT | GPIO7 | GPIO6 | GPIO5 | USB SUSPEND | 100221295rA | BOARD | DORADO | GND_BATT | INTERFACE | USB_VCC | SW | MAG | HOST | AUV | SMBUS | BATT_VCC | SBC | XCVR | PWR | PWR1 | PWR2 | CHASSIS | OUT | TRIG | IN | USB | BATTERY
XSECTION_CHART: L1: TOP CONDUCTOR - COPPER 2.7 MIL | *  DIELECTRIC - FR-4 5.1 MIL | *  DIELECTRIC - FR-4 4.3 MIL | L2: IN1 CONDUCTOR - COPPER 2.7 MIL | *  DIELECTRIC - FR-4 35 MIL | L3: IN2 CONDUCTOR - COPPER 2.7 MIL | L4: BOTTOM CONDUCTOR - COPPER 2.7 MIL | DESIGN CROSS SECTION CHART | ___________________________ | TOTAL THICKNESS 64.6 MIL | 1-4
DISPLAY_BOTTOM: FIGURE | FINISHED_SIZE | 15.0 | 32.0 | 34.0 | 35.0 | 38.0 | 44.0 | 47.0 | 59.0 | 65.0 | 67.0 | 73.0 | 126.0 | 89.0 | 110.2 | DRILL CHART: TOP to BOTTOM | ALL UNITS ARE IN MILS | PLATED | NON-PLATED | QTY | 234 | 6 | 12 | 4 | 11 | 2 | 1
